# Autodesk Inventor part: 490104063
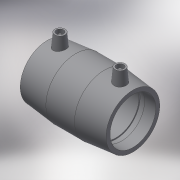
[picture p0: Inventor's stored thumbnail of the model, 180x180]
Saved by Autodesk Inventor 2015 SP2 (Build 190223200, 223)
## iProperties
Created: 2017-06
Part Number: 490104063
Material: Generic
Description: PLASSON COUPLER 63-63
Document SubType Name: Modeling
Designer: KIM
Mass: 217.95 g
Surface Area: 593.062 cm^2
Volume: 217.95 cm^3
Density: 1 g/cm^3
Appearance: Default
Author: KIM
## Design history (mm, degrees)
derived "490104.ipt"
feature "Solid1::490104.ipt"
tag "TaggingFeature1"
body "Solid1"
other parameters: "d0" = 118, "d1" = 63, "d2" = 82, "d3" = 58, "d4" = 39.33333, "d5" = 73.8, "d6" = 59.85, "d7" = 63, "d8" = 168 deg, "d10" = 23.2, "d11" = 7.73333, "d13" = 118, "d14" = 17.6296, "d15" = 58, "d16" = 58, "d17" = 59.85, "d18" = 63, "d19" = 3.52592, "d20" = 168 deg, "d22" = 77.08, "d23" = 82, "d24" = 74.7676, "d25" = 135 deg, "d26" = 47.2, "d27" = 135 deg, "d29" = 56, "d30" = 14, "d31" = 41.3, "d34" = 5 deg, "d35" = 15, "d39" = 5 deg, "d41" = 4, "d42" = 14, "d43" = 0, "d45" = 4, "d46" = 14, "d47" = 0, "d48" = 3, "d49" = 0, "d50" = 3, "d51" = 0, "d52" = 16.82, "d53" = 4.205, "d_" = 63, "L_" = 118, "L_1" = 58, "D_" = 82, "A_" = 56, "d_2" = 12
